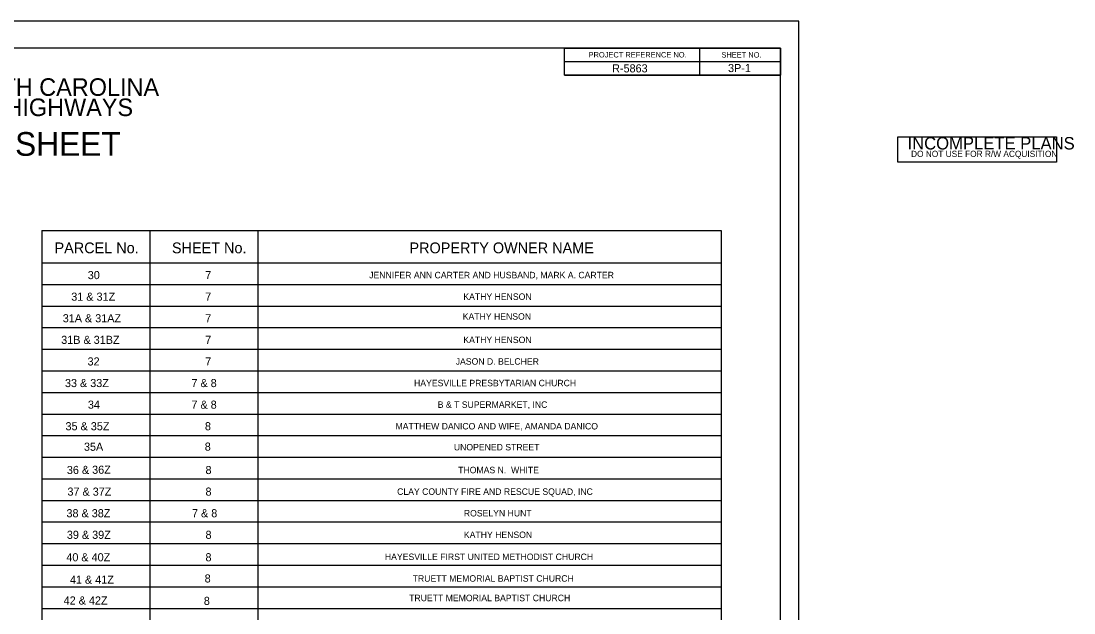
# Model space of a CAD drawing. Extents: x 811517 to 813456, y 643963 to 645063.
# Drawn here: x 812480 to 813456, y 644514 to 645063 of the extents above; entities that cross this region are included whole.
import ezdxf

# ---------------------------------------------------------------- set-up
doc = ezdxf.new("R2010")
doc.units = 0
for name, color, linetype in [('Old_Level_1', 7, 'Continuous'), ('Old_Level_2', 7, 'Continuous'), ('Sheet Data Field CELL', 7, 'Continuous'), ('Sheet Plot Border Outside CELL', 7, 'Continuous'), ('Sheet Sticker Incomplete CELL', 7, 'Continuous'), ('Sheet Summary CELL', 7, 'Continuous')]:
    doc.layers.add(name, color=color, linetype=linetype)

msp = doc.modelspace()

# ---------------------------------------------------------------- linework, layer by layer
at = {"layer": 'Sheet Plot Border Outside CELL'}
msp.add_lwpolyline([(813200.53, 645062.6), (811516.53, 645062.6), (811516.53, 643962.6), (813200.53, 643962.6)], close=True, dxfattribs=at)
at = {"layer": 'Sheet Sticker Incomplete CELL'}
msp.add_lwpolyline([(813292.38, 644931.97), (813292.38, 644955.47), (813439.38, 644955.47), (813439.38, 644931.97)], close=True, dxfattribs=at)
at = {"layer": 'Sheet Summary CELL'}
for p, q in [((813108.53, 645037.55), (813108.53, 645012.55)), ((812983.48, 645025.05), (813183.53, 645025.05)), ((812983.48, 645012.55), (813183.53, 645012.55)), ((812499.03, 644868.64), (813128.44, 644868.64)), ((812499.03, 644868.64), (812499.03, 644078.64)), ((812599.03, 644868.64), (812599.03, 644078.64)), ((812699.03, 644868.64), (812699.03, 644078.64)), ((813128.44, 644868.64), (813128.44, 644078.64)), ((812499.03, 644838.64), (813128.44, 644838.64)), ((812499.03, 644818.64), (813128.44, 644818.64)), ((812499.03, 644798.64), (813128.44, 644798.64)), ((812499.03, 644778.64), (813128.44, 644778.64)), ((812499.03, 644758.64), (813128.44, 644758.64)), ((812499.03, 644738.64), (813128.44, 644738.64)), ((812499.03, 644718.64), (813128.44, 644718.64)), ((812499.03, 644698.64), (813128.44, 644698.64)), ((812499.03, 644678.64), (813128.44, 644678.64)), ((812499.03, 644658.64), (813128.44, 644658.64)), ((812499.03, 644638.64), (813128.44, 644638.64)), ((812499.03, 644618.64), (813128.44, 644618.64)), ((812499.03, 644598.64), (813128.44, 644598.64)), ((812499.03, 644578.64), (813128.44, 644578.64)), ((812499.03, 644558.64), (813128.44, 644558.64)), ((812499.03, 644538.64), (813128.44, 644538.64)), ((812499.03, 644518.64), (813128.44, 644518.64))]:
    msp.add_line(p, q, dxfattribs=at)
for points in [[(813183.53, 645037.6), (811683.53, 645037.6), (811683.53, 643987.6), (813183.53, 643987.6)], [(812983.48, 645037.6), (813183.53, 645037.6), (813183.53, 645012.55), (812983.48, 645012.55)]]:
    msp.add_lwpolyline(points, close=True, dxfattribs=at)

# ---------------------------------------------------------------- texts
at = {"layer": 'Old_Level_1'}
for s, p in [('PARCEL No.', (812510.66, 644847.53)), ('SHEET No.', (812619.5, 644847.53)), ('PROPERTY OWNER NAME', (812839.67, 644847.53))]:
    msp.add_text(s, height=10, dxfattribs=at).set_placement(p)
at = {"layer": 'Old_Level_2'}
for s, height, p in [('30', 7.5, (812541.47, 644823.59)), ('7', 7.5, (812650.34, 644823.59)), ('JENNIFER ANN CARTER AND HUSBAND, MARK A. CARTER', 6, (812802.3, 644824.34)), ('31 & 31Z', 7.5, (812526.18, 644803.59)), ('7', 7.5, (812650.34, 644803.59)), ('KATHY HENSON', 6, (812889.58, 644804.34)), ('31A & 31AZ', 7.5, (812518.27, 644783.59)), ('7', 7.5, (812650.34, 644783.59)), ('KATHY HENSON', 6, (812889.05, 644786)), ('31B & 31BZ', 7.5, (812516.85, 644763.59)), ('7', 7.5, (812650.34, 644763.59)), ('KATHY HENSON', 6, (812889.58, 644764.34)), ('32', 7.5, (812541.27, 644743.59)), ('7', 7.5, (812650.34, 644743.59)), ('JASON D. BELCHER', 6, (812882.51, 644744.34)), ('33 & 33Z', 7.5, (812520.34, 644723.59)), ('7 & 8', 7.5, (812637.56, 644723.59)), ('HAYESVILLE PRESBYTARIAN CHURCH', 6, (812843.89, 644724.34)), ('34', 7.5, (812541.59, 644703.59)), ('7 & 8', 7.5, (812637.56, 644703.59)), ('B & T SUPERMARKET, INC', 6, (812865.86, 644704.34)), ('35 & 35Z', 7.5, (812520.87, 644683.59)), ('8', 7.5, (812650.08, 644683.59)), ('MATTHEW DANICO AND WIFE, AMANDA DANICO', 6, (812826.74, 644684.34)), ('35A', 7.5, (812537.95, 644664.6)), ('8', 7.5, (812649.91, 644664.71)), ('UNOPENED STREET', 6, (812880.8, 644664.93)), ('8', 7.5, (812650.61, 644643.02)), ('THOMAS N.  WHITE', 6, (812884.81, 644643.77)), ('37 & 37Z', 7.5, (812522.63, 644623.02)), ('8', 7.5, (812650.61, 644623.02)), ('CLAY COUNTY FIRE AND RESCUE SQUAD, INC', 6, (812828.22, 644623.77)), ('38 & 38Z', 7.5, (812521.75, 644603.02)), ('7 & 8', 7.5, (812638.09, 644603.02)), ('ROSELYN HUNT', 6, (812890.06, 644603.77)), ('39 & 39Z', 7.5, (812522.11, 644583.02)), ('8', 7.5, (812650.61, 644583.02)), ('KATHY HENSON', 6, (812890.1, 644583.77)), ('40 & 40Z', 7.5, (812521.62, 644562.24)), ('8', 7.5, (812650.58, 644562.24)), ('HAYESVILLE FIRST UNITED METHODIST CHURCH', 6, (812816.89, 644563.39)), ('41 & 41Z', 7.5, (812524.97, 644541.47)), ('8', 7.5, (812649.82, 644542.6)), ('TRUETT MEMORIAL BAPTIST CHURCH', 6, (812842.63, 644543.35)), ('TRUETT MEMORIAL BAPTIST CHURCH', 6, (812839.36, 644525.26)), ('42 & 42Z', 7.5, (812519.13, 644522.2)), ('8', 7.5, (812649.07, 644521.83))]:
    msp.add_text(s, height=height, dxfattribs=at).set_placement(p)
msp.add_text('36 & 36Z', height=7.5, rotation=0.54677, dxfattribs=at).set_placement((812522.15, 644643.01))
at = {"layer": 'Sheet Data Field CELL'}
for s, p in [('R-5863', (813027.51, 645015.05)), ('3P-1', (813134.95, 645015.35))]:
    msp.add_text(s, height=7.5, dxfattribs=at).set_placement(p)
at = {"layer": 'Sheet Sticker Incomplete CELL'}
for s, height, p in [('INCOMPLETE PLANS', 11.52, (813301.33, 644943.67)), ('DO NOT USE FOR R/W ACQUISITION', 5.76, (813304.58, 644936.72))]:
    msp.add_text(s, height=height, dxfattribs=at).set_placement(p)
at = {"layer": 'Sheet Summary CELL'}
for s, height, p in [('PROJECT REFERENCE NO.', 5.0001, (813005.68, 645028.9)), ('SHEET NO.', 5, (813128.83, 645028.8)), ('STATE OF NORTH CAROLINA', 16.2501, (812300.93, 644993.35)), ('DIVISION OF HIGHWAYS', 16.2501, (812327.53, 644974.6)), ('PARCEL INDEX SHEET', 21.9501, (812250.65, 644937.82))]:
    msp.add_text(s, height=height, dxfattribs=at).set_placement(p)

doc.saveas('drawing.dxf')
